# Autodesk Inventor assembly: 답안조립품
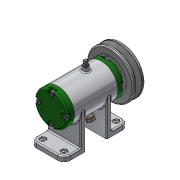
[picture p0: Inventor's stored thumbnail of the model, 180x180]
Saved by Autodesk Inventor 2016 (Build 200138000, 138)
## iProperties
Created: 2017-02
Part Number: 답안조립품
Material: 일반
Document SubType Name: Assembly
Designer: H
Author: H
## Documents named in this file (16)
- C:\Users\CAMTIC\Desktop\470207V1019\답안조립품.iam
- C:\Users\CAMTIC\Desktop\470207V1019\본체.ipt
- C:\Users\CAMTIC\Desktop\470207V1019\V벨트풀리.ipt
- C:\Users\CAMTIC\Desktop\470207V1019\너트 M 8.ipt
- C:\Users\CAMTIC\Desktop\470207V1019\니플 M 6 x 0.75.ipt
- C:\Users\CAMTIC\Desktop\470207V1019\뒤커버.ipt
- C:\Users\CAMTIC\Desktop\470207V1019\베어링 15 x 32 x 9.ipt
- C:\Users\CAMTIC\Desktop\470207V1019\볼트 M 6 x 8.ipt
- C:\Users\CAMTIC\Desktop\470207V1019\볼트 M4 x 12.ipt
- C:\Users\CAMTIC\Desktop\470207V1019\스프링와셔 8.ipt
- C:\Users\CAMTIC\Desktop\470207V1019\앞커버.ipt
- C:\Users\CAMTIC\Desktop\470207V1019\오일 실 15 25 7.ipt
- C:\Users\CAMTIC\Desktop\470207V1019\와셔 6x11.5.ipt
- C:\Users\CAMTIC\Desktop\470207V1019\와셔 8x17.ipt
- C:\Users\CAMTIC\Desktop\470207V1019\축.ipt
- C:\Users\CAMTIC\Desktop\470207V1019\키 3 x 3 x 12.ipt
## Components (11 placed, 3 different names)
1. V벨트풀리:1
2. KS B 2023 6002 - 15 x 32 x 9:1
3. KS B 2023 6002 - 15 x 32 x 9:2
4. ISO 4762 M4 x 12:2
5. ISO 4762 M4 x 12:3
6. ISO 4762 M4 x 12:4
7. ISO 4762 M4 x 12:5
8. ISO 4762 M4 x 12:1
9. ISO 4762 M4 x 12:6
10. ISO 4762 M4 x 12:7
11. ISO 4762 M4 x 12:8
